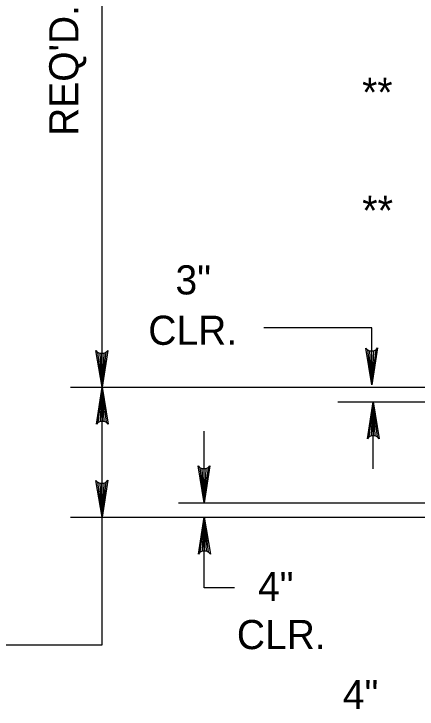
# Model space of a CAD drawing. Extents: x 639011 to 639866, y 298840 to 300028.
# Drawn here: x 639260.4 to 639301.8, y 299504.2 to 299575.8 of the extents above; entities that cross this region are included whole.
import ezdxf

# ---------------------------------------------------------------- set-up
doc = ezdxf.new("R2010")
doc.units = 0
doc.layers.add('2', color=7, linetype='Continuous')

msp = doc.modelspace()

# ---------------------------------------------------------------- linework, layer by layer
at = {"layer": '2'}
for p, q in [((639269.428, 299537.342), (639269.428, 299645.967)), ((639297.178, 299543.467), (639286.054, 299543.467)), ((639297.178, 299543.467), (639293.678, 299543.467)), ((639297.178, 299537.592), (639297.178, 299543.467)), ((639269.428, 299537.342), (639268.794, 299541.136)), ((639268.794, 299541.136), (639268.97, 299540.94)), ((639270.018, 299541.144), (639269.428, 299537.342)), ((639269.858, 299540.951), (639270.018, 299541.144)), ((639297.178, 299537.592), (639296.544, 299541.386)), ((639296.544, 299541.386), (639296.72, 299541.19)), ((639296.982, 299541.063), (639296.72, 299541.19)), ((639296.72, 299541.19), (639297.178, 299537.592)), ((639297.344, 299541.065), (639296.982, 299541.063)), ((639297.178, 299537.592), (639296.982, 299541.063)), ((639297.178, 299537.592), (639297.163, 299541.064)), ((639297.768, 299541.394), (639297.178, 299537.592)), ((639297.178, 299537.592), (639297.608, 299541.201)), ((639297.344, 299541.065), (639297.178, 299537.592)), ((639297.608, 299541.201), (639297.344, 299541.065)), ((639297.608, 299541.201), (639297.768, 299541.394)), ((639269.232, 299540.813), (639268.97, 299540.94)), ((639268.97, 299540.94), (639269.428, 299537.342)), ((639269.594, 299540.815), (639269.232, 299540.813)), ((639269.428, 299537.342), (639269.232, 299540.813)), ((639269.428, 299537.342), (639269.413, 299540.814)), ((639269.428, 299537.342), (639269.858, 299540.951)), ((639269.594, 299540.815), (639269.428, 299537.342)), ((639269.858, 299540.951), (639269.594, 299540.815)), ((639266.178, 299537.342), (639308.428, 299537.342)), ((639268.838, 299533.54), (639269.428, 299537.342)), ((639269.428, 299537.342), (639268.997, 299533.732)), ((639269.262, 299533.868), (639269.428, 299537.342)), ((639269.428, 299523.967), (639269.428, 299537.342)), ((639269.428, 299537.342), (639269.624, 299533.871)), ((639269.886, 299533.743), (639269.428, 299537.342)), ((639269.428, 299537.342), (639270.062, 299533.547)), ((639269.428, 299537.342), (639269.443, 299533.869)), ((639293.678, 299535.842), (639307.928, 299535.842)), ((639296.713, 299532.04), (639297.303, 299535.842)), ((639297.303, 299535.842), (639296.872, 299532.232)), ((639297.137, 299532.368), (639297.303, 299535.842)), ((639297.303, 299528.967), (639297.303, 299535.842)), ((639297.303, 299535.842), (639297.499, 299532.371)), ((639297.761, 299532.243), (639297.303, 299535.842)), ((639297.303, 299535.842), (639297.937, 299532.047)), ((639297.303, 299535.842), (639297.318, 299532.369)), ((639269.262, 299533.868), (639269.624, 299533.871)), ((639269.624, 299533.871), (639269.886, 299533.743)), ((639268.997, 299533.732), (639268.838, 299533.54)), ((639268.997, 299533.732), (639269.262, 299533.868)), ((639270.062, 299533.547), (639269.886, 299533.743)), ((639279.928, 299525.467), (639279.928, 299532.842)), ((639296.872, 299532.232), (639296.713, 299532.04)), ((639296.872, 299532.232), (639297.137, 299532.368)), ((639297.137, 299532.368), (639297.499, 299532.371)), ((639297.499, 299532.371), (639297.761, 299532.243)), ((639297.937, 299532.047), (639297.761, 299532.243)), ((639279.928, 299525.467), (639279.294, 299529.261)), ((639279.294, 299529.261), (639279.47, 299529.065)), ((639279.732, 299528.938), (639279.47, 299529.065)), ((639279.47, 299529.065), (639279.928, 299525.467)), ((639280.094, 299528.94), (639279.732, 299528.938)), ((639279.928, 299525.467), (639279.732, 299528.938)), ((639279.928, 299525.467), (639279.913, 299528.939)), ((639280.518, 299529.269), (639279.928, 299525.467)), ((639279.928, 299525.467), (639280.358, 299529.076)), ((639280.094, 299528.94), (639279.928, 299525.467)), ((639280.358, 299529.076), (639280.094, 299528.94)), ((639280.358, 299529.076), (639280.518, 299529.269)), ((639269.428, 299523.967), (639268.794, 299527.761)), ((639268.794, 299527.761), (639268.97, 299527.565)), ((639269.232, 299527.438), (639268.97, 299527.565)), ((639268.97, 299527.565), (639269.428, 299523.967)), ((639269.594, 299527.44), (639269.232, 299527.438)), ((639269.428, 299523.967), (639269.232, 299527.438)), ((639269.428, 299523.967), (639269.413, 299527.439)), ((639270.018, 299527.769), (639269.428, 299523.967)), ((639269.428, 299523.967), (639269.858, 299527.576)), ((639269.594, 299527.44), (639269.428, 299523.967)), ((639269.858, 299527.576), (639269.594, 299527.44)), ((639269.858, 299527.576), (639270.018, 299527.769)), ((639277.303, 299525.467), (639307.803, 299525.467)), ((639266.178, 299523.967), (639307.803, 299523.967)), ((639269.428, 299510.842), (639269.428, 299523.967)), ((639279.338, 299520.165), (639279.928, 299523.967)), ((639279.928, 299523.967), (639279.497, 299520.357)), ((639279.762, 299520.493), (639279.928, 299523.967)), ((639279.928, 299516.717), (639279.928, 299523.967)), ((639279.928, 299523.967), (639280.124, 299520.496)), ((639280.386, 299520.368), (639279.928, 299523.967)), ((639279.928, 299523.967), (639280.562, 299520.172)), ((639279.928, 299523.967), (639279.943, 299520.494)), ((639279.497, 299520.357), (639279.338, 299520.165)), ((639279.497, 299520.357), (639279.762, 299520.493)), ((639279.762, 299520.493), (639280.124, 299520.496)), ((639280.124, 299520.496), (639280.386, 299520.368)), ((639280.562, 299520.172), (639280.386, 299520.368)), ((639283.053, 299516.717), (639279.928, 299516.717)), ((639283.053, 299516.717), (639279.928, 299516.717)), ((639234.18, 299510.842), (639269.428, 299510.842)), ((639236.553, 299510.842), (639269.428, 299510.842))]:
    msp.add_line(p, q, dxfattribs=at)

# ---------------------------------------------------------------- texts
msp.add_text("REQ'D. STEM HEIGHT", height=3, rotation=90, dxfattribs=at).set_placement((639266.988, 299563.224))
for s, height, p in [('**', 3, (639296.178, 299566.217)), ('**', 3.0488, (639296.179, 299554.026)), ('3"', 3, (639276.978, 299546.904)), ('CLR.', 3, (639274.178, 299541.717)), ('4"', 3, (639285.463, 299515.342)), ('CLR.', 3, (639283.289, 299510.39)), ('4"', 3, (639294.188, 299504.217))]:
    msp.add_text(s, height=height, dxfattribs=at).set_placement(p)

doc.saveas('drawing.dxf')
